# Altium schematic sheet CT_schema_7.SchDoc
size 258 x 245 mm
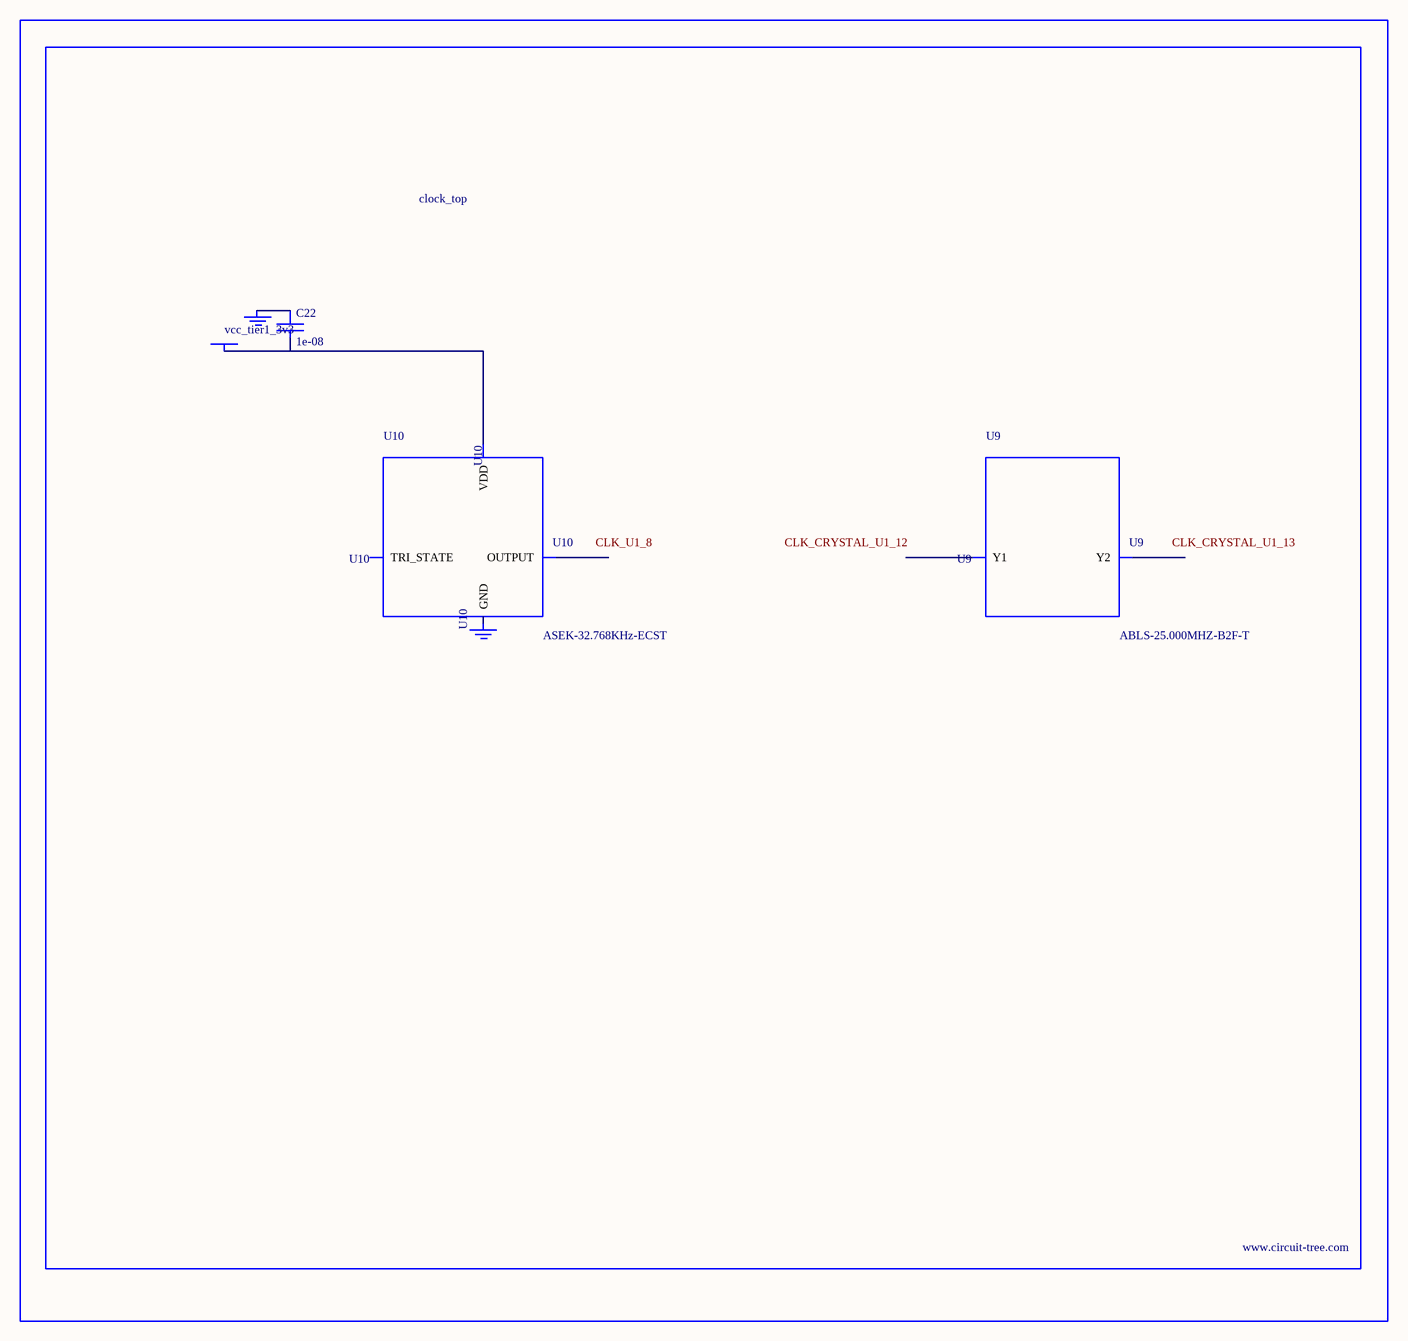
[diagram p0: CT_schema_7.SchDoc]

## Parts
BORDER6  (no value)
C22  1e-08  [C0402]
GND_INSTANCE_6_0  (no value)
GND_INSTANCE_6_1  (no value)
POWER_INSTANCE_6_0  vcc_tier1_3v3
U9  ABLS-25.000MHZ-B2F-T  [ABLS-25.000MHZ-B2F-T]
U10  ASEK-32.768KHz-ECST  [ASEK]

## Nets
NetC22_1: C22.1 GND_INSTANCE_6_0.0(GND)
NetC22_2: C22.2 POWER_INSTANCE_6_0.0(PWR) U10.4(VDD)

Not connected (* = marked no-connect by the designer): GND_INSTANCE_6_1 0(GND); U9 1(Y1) 2(Y2); U10 1(TRI_STATE) 2(GND) 3(OUTPUT)

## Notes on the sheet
- Labels drawn without touching a wire or pin: CLK_CRYSTAL_U1_12, CLK_CRYSTAL_U1_13, CLK_U1_8

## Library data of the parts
BORDER6 = BORDER_PAGE6
C22 = C0402C103K3RAC
GND_INSTANCE_6_0 GND_INSTANCE_6_1 = GND
POWER_INSTANCE_6_0 = PWR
